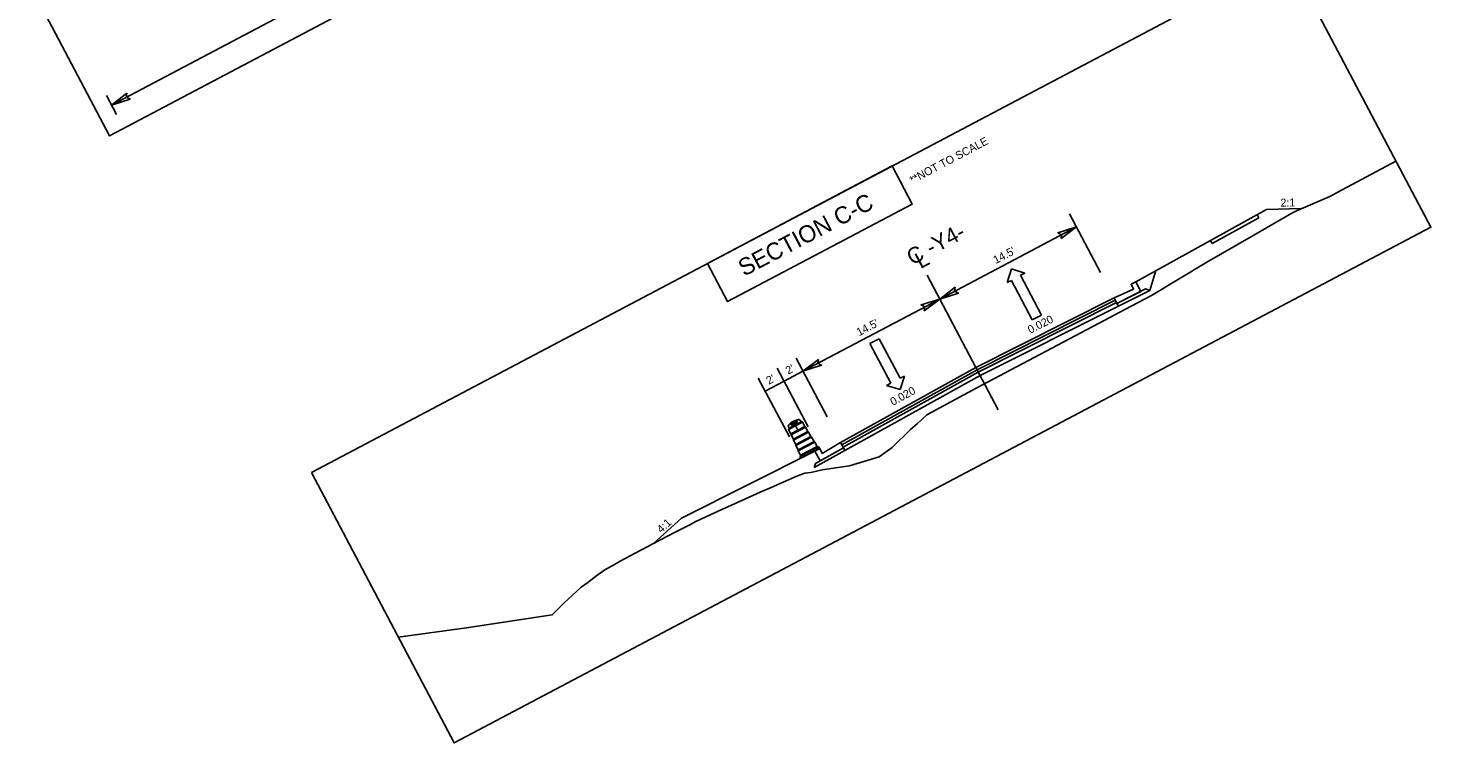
# Model space of a CAD drawing. Extents: x 1487176 to 1495274, y 497106 to 503692.
# Drawn here: x 1488684.4 to 1488815.9, y 497105.6 to 497172.6 of the extents above; entities that cross this region are included whole.
import ezdxf

# ---------------------------------------------------------------- set-up
doc = ezdxf.new("R2010")
doc.units = 0
for name, color, linetype in [('Default', 7, 'Continuous'), ('Exist XS Ground Line', 7, 'Continuous'), ('Prop Terminator CELL', 7, 'Continuous'), ('Typical Hinge Slope Interstate CELL', 7, 'Continuous'), ('WZ OSDR CELL', 7, 'Continuous')]:
    doc.layers.add(name, color=color, linetype=linetype)

msp = doc.modelspace()

# ---------------------------------------------------------------- linework, layer by layer
at = {"layer": 'Default'}
for p, q in [((1488766.66, 497204.67), (1488692.23, 497165.37)), ((1488692.69, 497164.49), (1488691.76, 497166.26)), ((1488784.96, 497149.68), (1488782.05, 497155.19)), ((1488782.7, 497153.96), (1488769.88, 497147.19)), ((1488799.78, 497154.8), (1488799.63, 497155.1)), ((1488795.41, 497152.38), (1488795.25, 497152.68)), ((1488776.6, 497150.02), (1488776.19, 497148.73)), ((1488777.86, 497149.62), (1488776.6, 497150.02)), ((1488775.36, 497136.8), (1488768.71, 497149.41)), ((1488776.19, 497148.73), (1488776.59, 497148.94)), ((1488776.59, 497148.94), (1488778.55, 497145.23)), ((1488777.46, 497149.41), (1488777.86, 497149.62)), ((1488779.43, 497145.69), (1488777.46, 497149.41)), ((1488769.88, 497147.19), (1488757.05, 497140.42)), ((1488778.55, 497145.23), (1488779.43, 497145.69)), ((1488763.32, 497143.01), (1488764.2, 497143.47)), ((1488764.2, 497143.47), (1488766.16, 497139.76)), ((1488765.29, 497139.3), (1488763.32, 497143.01)), ((1488757.54, 497135.21), (1488754.64, 497140.71)), ((1488759.31, 497136.14), (1488756.41, 497141.64)), ((1488755.78, 497134.27), (1488752.87, 497139.78)), ((1488753.52, 497138.55), (1488755.29, 497139.49)), ((1488755.29, 497139.49), (1488757.05, 497140.42)), ((1488766.16, 497139.76), (1488766.56, 497139.97)), ((1488766.56, 497139.97), (1488766.18, 497138.7)), ((1488764.89, 497139.09), (1488765.29, 497139.3)), ((1488766.18, 497138.7), (1488764.89, 497139.09))]:
    msp.add_line(p, q, dxfattribs=at)
for points in [[(1488676.52, 497191.9), (1488777.22, 497245.07), (1488792.75, 497215.65), (1488692.05, 497162.48)], [(1488710.97, 497130.93), (1488802.54, 497179.28), (1488815.93, 497153.92), (1488724.36, 497105.57)], [(1488748.1, 497150.53), (1488765.41, 497159.68), (1488767.3, 497156.09), (1488749.99, 497146.95)], [(1488773.38, 497140.56), (1488773.32, 497140.67), (1488773.32, 497140.67), (1488773.38, 497140.56)], [(1488773.38, 497140.56), (1488773.32, 497140.67), (1488773.32, 497140.67), (1488773.38, 497140.56)]]:
    msp.add_lwpolyline(points, close=True, dxfattribs=at)
for points in [[(1488788.25, 497148.8), (1488800.5, 497155.58), (1488803.76, 497155.66)], [(1488795.41, 497152.38), (1488799.78, 497154.8)], [(1488786.22, 497147.3), (1488788.04, 497148.12), (1488787.81, 497148.57), (1488788.25, 497148.8)], [(1488788.25, 497148.8), (1488788.72, 497147.9), (1488786.49, 497146.78)], [(1488786.63, 497146.52), (1488789.57, 497148), (1488790.14, 497149.85)], [(1488788.04, 497148.12), (1488787.81, 497148.57), (1488788.25, 497148.8)], [(1488773.26, 497140.78), (1488786.22, 497147.3)], [(1488773.26, 497140.78), (1488786.22, 497147.3)], [(1488786.22, 497147.3), (1488788.04, 497148.12)], [(1488786.49, 497146.78), (1488786.22, 497147.3)], [(1488786.22, 497147.3), (1488786.33, 497147.07)], [(1488786.49, 497146.78), (1488789.17, 497148.13), (1488789.57, 497148)], [(1488789.57, 497148), (1488786.63, 497146.52)], [(1488773.38, 497140.56), (1488786.33, 497147.07)], [(1488786.33, 497147.07), (1488773.38, 497140.56)], [(1488786.45, 497146.85), (1488773.49, 497140.34)], [(1488773.49, 497140.34), (1488786.45, 497146.85)], [(1488786.63, 497146.52), (1488773.67, 497140.01)], [(1488773.67, 497140.01), (1488786.63, 497146.52)], [(1488786.33, 497147.07), (1488786.45, 497146.85)], [(1488786.45, 497146.85), (1488786.63, 497146.52)], [(1488786.63, 497146.52), (1488786.49, 497146.78)], [(1488773.26, 497140.78), (1488760.57, 497133.75)], [(1488773.38, 497140.56), (1488773.26, 497140.78)], [(1488773.38, 497140.56), (1488773.26, 497140.78)], [(1488773.38, 497140.56), (1488760.69, 497133.53)], [(1488760.69, 497133.53), (1488773.38, 497140.56)], [(1488760.81, 497133.31), (1488773.49, 497140.34)], [(1488773.49, 497140.34), (1488760.81, 497133.31)], [(1488760.98, 497132.98), (1488773.67, 497140.01)], [(1488773.67, 497140.01), (1488760.98, 497132.98)], [(1488773.49, 497140.34), (1488773.38, 497140.56)], [(1488773.49, 497140.34), (1488773.38, 497140.56)], [(1488773.67, 497140.01), (1488773.49, 497140.34)], [(1488773.67, 497140.01), (1488773.49, 497140.34)], [(1488758.18, 497132.92), (1488745.67, 497126.63), (1488743.03, 497124.27)], [(1488760.85, 497133.24), (1488758.22, 497131.78), (1488758.1, 497131.38)], [(1488758.1, 497131.38), (1488760.98, 497132.98)], [(1488760.57, 497133.75), (1488758.86, 497132.71), (1488758.63, 497133.16), (1488758.18, 497132.92)], [(1488758.18, 497132.92), (1488758.66, 497132.03), (1488760.85, 497133.24)], [(1488758.86, 497132.71), (1488758.63, 497133.16), (1488758.18, 497132.92)], [(1488760.57, 497133.75), (1488758.86, 497132.71)], [(1488760.85, 497133.24), (1488760.57, 497133.75)], [(1488760.57, 497133.75), (1488760.69, 497133.53)], [(1488760.69, 497133.53), (1488760.81, 497133.31)], [(1488760.81, 497133.31), (1488760.98, 497132.98)], [(1488760.98, 497132.98), (1488760.85, 497133.24)]]:
    msp.add_lwpolyline(points, dxfattribs=at)
at = {"layer": 'Exist XS Ground Line'}
msp.add_lwpolyline([(1488719.12, 497115.5), (1488725.52, 497116.37), (1488733.55, 497117.57), (1488734.65, 497118.69), (1488736.25, 497120.16), (1488736.89, 497120.6), (1488737.73, 497121.27), (1488738.48, 497121.8), (1488739.39, 497122.3), (1488739.93, 497122.6), (1488741.33, 497123.35), (1488742.5, 497123.98), (1488742.93, 497124.21), (1488743.65, 497124.59), (1488745.09, 497125.34), (1488746.34, 497125.97), (1488747.02, 497126.32), (1488747.96, 497126.77), (1488749.46, 497127.45), (1488750.36, 497127.87), (1488752.36, 497128.77), (1488753.03, 497129.07), (1488754.06, 497129.52), (1488755.71, 497130.25), (1488756.25, 497130.48), (1488756.8, 497130.7), (1488757.24, 497130.86), (1488757.79, 497130.91), (1488758.86, 497131.19), (1488761.43, 497131.55), (1488764.21, 497132.39), (1488765.42, 497133.27), (1488767.13, 497134.97), (1488767.8, 497135.53), (1488768.67, 497136.33), (1488771.4, 497137.8), (1488773.3, 497138.83), (1488785.3, 497145.17), (1488787.22, 497146.2), (1488789.73, 497147.51), (1488794.93, 497150.65), (1488799.33, 497153.19), (1488802.87, 497155.24), (1488803.33, 497155.47), (1488806.45, 497156.8), (1488807.13, 497157.16), (1488812.65, 497160.12)], dxfattribs=at)
at = {"layer": 'Prop Terminator CELL'}
for points in [[(1488693.67, 497166.49), (1488692.23, 497165.37), (1488693.98, 497165.93), (1488693.62, 497166.11)], [(1488781.25, 497152.85), (1488782.7, 497153.96), (1488780.95, 497153.4), (1488781.3, 497153.22)], [(1488771.32, 497148.3), (1488769.88, 497147.19), (1488771.63, 497147.75), (1488771.27, 497147.93)], [(1488768.43, 497146.08), (1488769.88, 497147.19), (1488768.13, 497146.63), (1488768.48, 497146.45)], [(1488758.5, 497141.53), (1488757.05, 497140.42), (1488758.8, 497140.98), (1488758.45, 497141.16)]]:
    msp.add_lwpolyline(points, close=True, dxfattribs=at)
at = {"layer": 'WZ OSDR CELL'}
for p, q in [((1488755.71, 497134.96), (1488757.01, 497135.65)), ((1488755.77, 497135.08), (1488756.88, 497135.67)), ((1488756.51, 497135.69), (1488756.51, 497135.7)), ((1488756.88, 497135.67), (1488756.81, 497135.8)), ((1488757.01, 497135.65), (1488757.23, 497135.23)), ((1488755.77, 497135.08), (1488755.7, 497135.21)), ((1488755.71, 497134.96), (1488755.93, 497134.55)), ((1488755.93, 497134.55), (1488757.23, 497135.23)), ((1488755.93, 497134.55), (1488755.94, 497134.46)), ((1488755.94, 497134.46), (1488757.3, 497135.18)), ((1488755.94, 497134.46), (1488756.16, 497134.05)), ((1488755.96, 497135.4), (1488755.95, 497135.41)), ((1488756.16, 497134.05), (1488757.52, 497134.76)), ((1488756.16, 497133.96), (1488757.58, 497134.71)), ((1488756.38, 497133.54), (1488757.8, 497134.3)), ((1488756.39, 497133.46), (1488757.87, 497134.24)), ((1488757.23, 497135.23), (1488757.3, 497135.18)), ((1488757.3, 497135.18), (1488757.52, 497134.76)), ((1488757.52, 497134.76), (1488757.58, 497134.71)), ((1488757.58, 497134.71), (1488757.8, 497134.3)), ((1488757.8, 497134.3), (1488757.87, 497134.24)), ((1488757.87, 497134.24), (1488758.09, 497133.83)), ((1488756.16, 497134.05), (1488756.16, 497133.96)), ((1488756.16, 497133.96), (1488756.38, 497133.54)), ((1488756.38, 497133.54), (1488756.39, 497133.46)), ((1488756.39, 497133.46), (1488756.61, 497133.04)), ((1488756.61, 497133.04), (1488758.09, 497133.83)), ((1488756.61, 497132.96), (1488758.16, 497133.77)), ((1488756.61, 497133.04), (1488756.61, 497132.96)), ((1488756.61, 497132.96), (1488756.83, 497132.54)), ((1488756.83, 497132.54), (1488758.38, 497133.36)), ((1488756.83, 497132.45), (1488758.46, 497133.31)), ((1488756.83, 497132.28), (1488758.6, 497133.21)), ((1488758.09, 497133.83), (1488758.16, 497133.77)), ((1488758.16, 497133.77), (1488758.38, 497133.36)), ((1488758.38, 497133.36), (1488758.45, 497133.31)), ((1488758.6, 497133.21), (1488758.56, 497133.28)), ((1488756.83, 497132.28), (1488756.79, 497132.35)), ((1488756.83, 497132.54), (1488756.84, 497132.46))]:
    msp.add_line(p, q, dxfattribs=at)
for points in [[(1488755.94, 497134.46), (1488756.62, 497134.82), (1488756.25, 497135.51), (1488756.22, 497135.5), (1488756.19, 497135.48), (1488756.17, 497135.47), (1488756.14, 497135.45), (1488756.11, 497135.43), (1488756.08, 497135.41), (1488756.05, 497135.39), (1488756.03, 497135.38), (1488756.02, 497135.37), (1488756, 497135.37), (1488755.99, 497135.37), (1488755.98, 497135.38), (1488755.97, 497135.38), (1488755.96, 497135.39), (1488755.95, 497135.41), (1488755.95, 497135.42), (1488755.95, 497135.44), (1488755.95, 497135.45), (1488755.96, 497135.47), (1488755.97, 497135.48), (1488755.99, 497135.49), (1488756.02, 497135.51), (1488756.09, 497135.56), (1488756.14, 497135.59), (1488756.18, 497135.61), (1488756.2, 497135.62), (1488756.15, 497135.7), (1488756.11, 497135.69), (1488756.07, 497135.66), (1488756.02, 497135.63), (1488755.98, 497135.6), (1488755.93, 497135.57), (1488755.88, 497135.53), (1488755.83, 497135.49), (1488755.8, 497135.46), (1488755.75, 497135.42), (1488755.73, 497135.4), (1488755.72, 497135.38), (1488755.71, 497135.37), (1488755.7, 497135.35), (1488755.69, 497135.32), (1488755.68, 497135.3), (1488755.68, 497135.28), (1488755.69, 497135.26), (1488755.69, 497135.24), (1488755.7, 497135.21), (1488755.77, 497135.08), (1488755.76, 497135.07), (1488755.75, 497135.06), (1488755.74, 497135.04), (1488755.73, 497135.02), (1488755.72, 497135), (1488755.71, 497134.96), (1488755.93, 497134.55)], [(1488757.3, 497135.18), (1488756.62, 497134.82), (1488756.25, 497135.51), (1488756.31, 497135.54), (1488756.35, 497135.56), (1488756.39, 497135.58), (1488756.42, 497135.59), (1488756.45, 497135.6), (1488756.48, 497135.61), (1488756.49, 497135.62), (1488756.5, 497135.63), (1488756.51, 497135.64), (1488756.52, 497135.66), (1488756.52, 497135.67), (1488756.52, 497135.69), (1488756.51, 497135.7), (1488756.5, 497135.71), (1488756.48, 497135.72), (1488756.47, 497135.73), (1488756.46, 497135.73), (1488756.45, 497135.73), (1488756.44, 497135.72), (1488756.42, 497135.72), (1488756.39, 497135.71), (1488756.37, 497135.7), (1488756.34, 497135.69), (1488756.31, 497135.67), (1488756.27, 497135.66), (1488756.25, 497135.64), (1488756.22, 497135.63), (1488756.2, 497135.62), (1488756.15, 497135.7), (1488756.19, 497135.73), (1488756.22, 497135.74), (1488756.27, 497135.76), (1488756.3, 497135.78), (1488756.34, 497135.79), (1488756.38, 497135.81), (1488756.43, 497135.82), (1488756.47, 497135.84), (1488756.53, 497135.85), (1488756.58, 497135.86), (1488756.62, 497135.87), (1488756.64, 497135.88), (1488756.66, 497135.88), (1488756.68, 497135.88), (1488756.7, 497135.88), (1488756.72, 497135.87), (1488756.74, 497135.87), (1488756.76, 497135.86), (1488756.77, 497135.84), (1488756.79, 497135.83), (1488756.8, 497135.82), (1488756.81, 497135.8), (1488756.81, 497135.8), (1488756.88, 497135.67), (1488756.91, 497135.67), (1488756.93, 497135.67), (1488756.95, 497135.67), (1488756.97, 497135.66), (1488756.99, 497135.66), (1488757, 497135.65), (1488757.01, 497135.65), (1488757.23, 497135.23)], [(1488756.16, 497134.05), (1488757.52, 497134.76), (1488757.58, 497134.71), (1488757.8, 497134.3), (1488757.87, 497134.24), (1488756.39, 497133.46), (1488756.38, 497133.54), (1488756.16, 497133.96)], [(1488756.61, 497133.04), (1488758.09, 497133.83), (1488758.16, 497133.77), (1488758.38, 497133.36), (1488758.45, 497133.31), (1488758.46, 497133.32), (1488758.48, 497133.32), (1488758.49, 497133.32), (1488758.51, 497133.32), (1488758.52, 497133.32), (1488758.53, 497133.31), (1488758.54, 497133.3), (1488758.55, 497133.29), (1488758.56, 497133.28), (1488758.56, 497133.28), (1488758.6, 497133.21), (1488756.83, 497132.28), (1488756.79, 497132.35), (1488756.79, 497132.36), (1488756.79, 497132.37), (1488756.79, 497132.38), (1488756.79, 497132.39), (1488756.79, 497132.4), (1488756.79, 497132.42), (1488756.8, 497132.43), (1488756.81, 497132.44), (1488756.82, 497132.44), (1488756.83, 497132.45), (1488756.84, 497132.46), (1488756.83, 497132.54), (1488756.61, 497132.96)]]:
    msp.add_lwpolyline(points, close=True, dxfattribs=at)
for centre, radius, start, end in [((1488756.98, 497134.14), 1.77, 100.8859, 134.7843), ((1488756, 497135.43), 0.0548, 126.5091, 207.8351), ((1488757.02, 497134.05), 1.77, 109.1611, 126.5091), ((1488757.08, 497133.95), 1.77, 109.6863, 125.9838), ((1488756.46, 497135.67), 0.0548, 27.8351, 109.1611), ((1488756.46, 497135.67), 0.0548, 289.6863, 27.8351), ((1488756.67, 497135.72), 0.157, 27.8351, 100.8859), ((1488756.9, 497135.4), 0.271, 67.3216, 95.5291), ((1488755.84, 497135.29), 0.157, 134.7843, 207.8351), ((1488755.98, 497134.91), 0.271, 140.1411, 168.3486), ((1488756.01, 497135.43), 0.0548, 207.8351, 305.9838), ((1488758.49, 497133.24), 0.0783, 27.8351, 117.8351), ((1488756.86, 497132.38), 0.0783, 117.8351, 207.8351)]:
    msp.add_arc(centre, radius, start, end, dxfattribs=at)

# ---------------------------------------------------------------- texts
at = {"layer": 'Default'}
for s, height, rotation, p in [('**NOT TO SCALE', 0.75, 27.8351, (1488767.3, 497157.96)), ('SECTION C-C', 1.6, 27.8351, (1488751.53, 497149.27)), ('2:1', 0.75, 1.27, (1488801.82, 497155.84)), ("14.5'", 0.75, 27.8351, (1488775.14, 497150.46)), ("14.5'", 0.75, 27.8351, (1488762.32, 497143.69)), ('0.020', 0.75, 26.6893, (1488778.36, 497143.92)), ("2'", 0.75, 27.8351, (1488755.67, 497140.09)), ("2'", 0.75, 27.8351, (1488753.85, 497139.15)), ('0.020', 0.75, 28.9809, (1488765.49, 497137.16)), ('4:1', 0.75, 41.8713, (1488743.76, 497125.2))]:
    msp.add_text(s, height=height, rotation=rotation, dxfattribs=at).set_placement(p)
at = {"layer": 'Typical Hinge Slope Interstate CELL'}
for s, p in [('C -Y4- ', (1488767.29, 497150.32)), ('L', (1488768.07, 497149.99))]:
    msp.add_text(s, height=1.5, rotation=27.8351, dxfattribs=at).set_placement(p)

doc.saveas('drawing.dxf')
